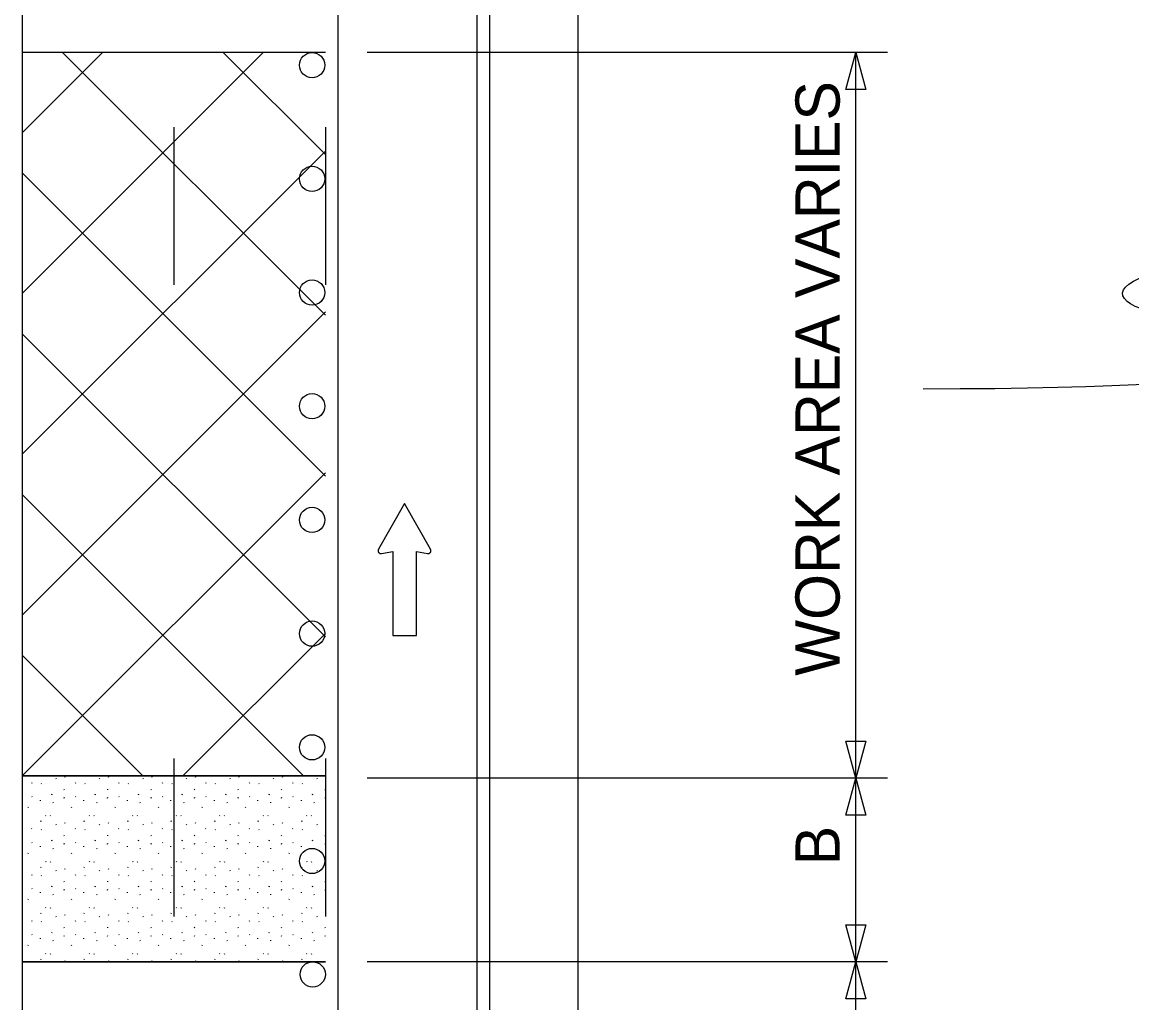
# Model space of a CAD drawing. Extents: x 16782 to 19504, y 6935 to 8243.
# Drawn here: x 17983.1 to 18158.8, y 7895 to 8050.2 of the extents above; entities that cross this region are included whole.
import ezdxf

# ---------------------------------------------------------------- set-up
doc = ezdxf.new("R2010")
doc.units = 0
for name, color, linetype in [('ALI_LEGAL_EX', 7, 'Continuous'), ('MT_SCRATCH_LEVEL_A', 7, 'Continuous'), ('MT_SCRATCH_LEVEL_E', 7, 'Continuous'), ('PAVT_EDGE_EX', 7, 'Continuous'), ('TRAFFIC_SIGNS_PR', 7, 'Continuous'), ('TYPICAL_TEXT_DIMEN_PR', 7, 'Continuous')]:
    doc.layers.add(name, color=color, linetype=linetype)

msp = doc.modelspace()

# ---------------------------------------------------------------- linework, layer by layer
at = {"layer": 'ALI_LEGAL_EX'}
for p, q in [((18033.11, 8234.45), (18033.11, 7405.27)), ((18057.11, 8234.45), (18057.11, 7405.27)), ((18057.11, 8234.45), (18057.11, 7405.27))]:
    msp.add_line(p, q, dxfattribs=at)
for points in [[(18007.13, 8033.65), (18007.13, 8008.65)], [(18031.13, 8033.65), (18031.13, 8008.65)], [(18007.13, 7933.65), (18007.13, 7908.65)], [(18031.13, 7933.65), (18031.13, 7908.65)]]:
    msp.add_lwpolyline(points, dxfattribs=at)
at = {"layer": 'MT_SCRATCH_LEVEL_A'}
for p, q in [((18031.13, 8045.46), (17983.13, 8045.46)), ((18031.13, 7930.92), (17983.13, 7930.92)), ((18031.13, 7901.49), (17983.13, 7901.49))]:
    msp.add_line(p, q, dxfattribs=at)
at = {"layer": 'MT_SCRATCH_LEVEL_E'}
for p, q in [((18043.65, 7974.03), (18039.54, 7966.79)), ((18047.8, 7966.79), (18043.65, 7974.03)), ((18040.03, 7966.11), (18041.8, 7966.42)), ((18041.8, 7966.42), (18041.8, 7953.17)), ((18045.54, 7953.17), (18045.54, 7966.42)), ((18045.54, 7966.42), (18047.32, 7966.11)), ((18041.8, 7953.17), (18045.54, 7953.17))]:
    msp.add_line(p, q, dxfattribs=at)
for centre, start, end in [((18039.95, 7966.57), 150.4248, 279.9638), ((18047.39, 7966.57), 260.0362, 29.7731)]:
    msp.add_arc(centre, 0.463, start, end, dxfattribs=at)
at = {"layer": 'PAVT_EDGE_EX'}
for p, q in [((17983.13, 8183.26), (17983.13, 7404.46)), ((18055.13, 8183.26), (18055.13, 7404.46)), ((18071.13, 8183.26), (18071.13, 7404.46)), ((18031.13, 8045.46), (17983.13, 8045.46)), ((17983.13, 8045.46), (17983.13, 7930.92)), ((17983.13, 8032.74), (17995.84, 8045.46)), ((17983.13, 8007.29), (18021.3, 8045.46)), ((18031.13, 8003.84), (17989.51, 8045.46)), ((18031.13, 8029.29), (18014.96, 8045.46)), ((17983.13, 7981.83), (18031.13, 8029.83)), ((18031.13, 7978.38), (17983.13, 8026.38)), ((17983.13, 7956.38), (18031.13, 8004.38)), ((18031.13, 7952.93), (17983.13, 8000.93)), ((17983.13, 7930.92), (18031.13, 7978.92)), ((18027.67, 7930.92), (17983.13, 7975.47)), ((18008.58, 7930.92), (18031.13, 7953.47)), ((18002.22, 7930.92), (17983.13, 7950.01)), ((17983.13, 7930.92), (18031.13, 7930.92)), ((18031.13, 7930.92), (17983.13, 7930.92)), ((17983.13, 7930.92), (17983.13, 7901.49)), ((17983.13, 7930.92), (17983.13, 7930.92)), ((17984.62, 7929.87), (17984.68, 7929.79)), ((17986.15, 7929.73), (17986.21, 7929.65)), ((17988.44, 7930.55), (17988.5, 7930.47)), ((17989.89, 7930.7), (17989.94, 7930.82)), ((17991.51, 7929.87), (17991.56, 7929.79)), ((17993.04, 7929.73), (17993.09, 7929.65)), ((17995.33, 7930.55), (17995.38, 7930.47)), ((17996.78, 7930.7), (17996.83, 7930.82)), ((17998.4, 7929.87), (17998.45, 7929.79)), ((17999.93, 7929.73), (17999.98, 7929.65)), ((18002.22, 7930.55), (18002.27, 7930.47)), ((18003.67, 7930.7), (18003.72, 7930.82)), ((18005.29, 7929.87), (18005.34, 7929.79)), ((18006.82, 7929.73), (18006.87, 7929.65)), ((18009.11, 7930.55), (18009.16, 7930.47)), ((18010.56, 7930.7), (18010.61, 7930.82)), ((18012.17, 7929.87), (18012.23, 7929.79)), ((18013.7, 7929.73), (18013.76, 7929.65)), ((18015.99, 7930.55), (18016.05, 7930.47)), ((18017.44, 7930.7), (18017.49, 7930.82)), ((18019.06, 7929.87), (18019.11, 7929.79)), ((18020.59, 7929.73), (18020.64, 7929.65)), ((18022.88, 7930.55), (18022.93, 7930.47)), ((18024.33, 7930.7), (18024.38, 7930.82)), ((18025.95, 7929.87), (18026, 7929.79)), ((18027.48, 7929.73), (18027.53, 7929.65)), ((18029.77, 7930.55), (18029.82, 7930.47)), ((17987.8, 7927.94), (17987.85, 7928.06)), ((17989.72, 7928.81), (17989.77, 7928.73)), ((17994.68, 7927.94), (17994.74, 7928.06)), ((17996.61, 7928.81), (17996.66, 7928.73)), ((18001.57, 7927.94), (18001.62, 7928.06)), ((18003.5, 7928.81), (18003.55, 7928.73)), ((18008.46, 7927.94), (18008.51, 7928.06)), ((18010.38, 7928.81), (18010.44, 7928.73)), ((18015.35, 7927.94), (18015.4, 7928.06)), ((18017.27, 7928.81), (18017.32, 7928.73)), ((18022.23, 7927.94), (18022.28, 7928.06)), ((18024.16, 7928.81), (18024.21, 7928.73)), ((18029.12, 7927.94), (18029.17, 7928.06)), ((18031.05, 7928.81), (18031.1, 7928.73)), ((17984.67, 7927.66), (17984.72, 7927.58)), ((17985.95, 7927.09), (17985.97, 7926.97)), ((17987.98, 7926.74), (17988.04, 7926.66)), ((17989.76, 7927.41), (17989.81, 7927.53)), ((17991.56, 7927.66), (17991.61, 7927.58)), ((17992.84, 7927.09), (17992.85, 7926.97)), ((17994.87, 7926.74), (17994.92, 7926.66)), ((17996.65, 7927.41), (17996.7, 7927.53)), ((17998.45, 7927.66), (17998.5, 7927.58)), ((17999.73, 7927.09), (17999.74, 7926.97)), ((18001.76, 7926.74), (18001.81, 7926.66)), ((18003.54, 7927.41), (18003.59, 7927.53)), ((18005.33, 7927.66), (18005.39, 7927.58)), ((18006.62, 7927.09), (18006.63, 7926.97)), ((18008.65, 7926.74), (18008.7, 7926.66)), ((18010.43, 7927.41), (18010.48, 7927.53)), ((18012.22, 7927.66), (18012.27, 7927.58)), ((18013.5, 7927.09), (18013.52, 7926.97)), ((18015.53, 7926.74), (18015.59, 7926.66)), ((18017.31, 7927.41), (18017.37, 7927.53)), ((18019.11, 7927.66), (18019.16, 7927.58)), ((18020.39, 7927.09), (18020.4, 7926.97)), ((18022.42, 7926.74), (18022.47, 7926.66)), ((18024.2, 7927.41), (18024.25, 7927.53)), ((18026, 7927.66), (18026.05, 7927.58)), ((18027.28, 7927.09), (18027.29, 7926.97)), ((18029.31, 7926.74), (18029.36, 7926.66)), ((18031.09, 7927.41), (18031.13, 7927.5)), ((17984.05, 7925.91), (17984.11, 7926.03)), ((17986.84, 7924.67), (17986.89, 7924.6)), ((17987.58, 7924.64), (17987.63, 7924.57)), ((17990.94, 7925.91), (17990.99, 7926.03)), ((17993.73, 7924.67), (17993.78, 7924.6)), ((17994.46, 7924.64), (17994.51, 7924.57)), ((17997.83, 7925.91), (17997.88, 7926.03)), ((18000.61, 7924.67), (18000.67, 7924.6)), ((18001.35, 7924.64), (18001.4, 7924.57)), ((18004.72, 7925.91), (18004.77, 7926.03)), ((18007.5, 7924.67), (18007.55, 7924.6)), ((18008.24, 7924.64), (18008.29, 7924.57)), ((18011.6, 7925.91), (18011.66, 7926.03)), ((18014.39, 7924.67), (18014.44, 7924.6)), ((18015.12, 7924.64), (18015.18, 7924.57)), ((18018.49, 7925.91), (18018.54, 7926.03)), ((18021.28, 7924.67), (18021.33, 7924.6)), ((18022.01, 7924.64), (18022.06, 7924.57)), ((18025.38, 7925.91), (18025.43, 7926.03)), ((18028.16, 7924.67), (18028.22, 7924.6)), ((18028.9, 7924.64), (18028.95, 7924.57)), ((17984.62, 7922.59), (17984.68, 7922.51)), ((17986.07, 7923.71), (17986.13, 7923.83)), ((17988.44, 7923.26), (17988.5, 7923.19)), ((17989.89, 7923.41), (17989.94, 7923.53)), ((17991.51, 7922.59), (17991.56, 7922.51)), ((17992.96, 7923.71), (17993.01, 7923.83)), ((17995.33, 7923.26), (17995.38, 7923.19)), ((17996.78, 7923.41), (17996.83, 7923.53)), ((17998.4, 7922.59), (17998.45, 7922.51)), ((17999.85, 7923.71), (17999.9, 7923.83)), ((18002.22, 7923.26), (18002.27, 7923.19)), ((18003.67, 7923.41), (18003.72, 7923.53)), ((18005.29, 7922.59), (18005.34, 7922.51)), ((18006.74, 7923.71), (18006.79, 7923.83)), ((18009.11, 7923.26), (18009.16, 7923.19)), ((18010.56, 7923.41), (18010.61, 7923.53)), ((18012.17, 7922.59), (18012.23, 7922.51)), ((18013.62, 7923.71), (18013.68, 7923.83)), ((18015.99, 7923.26), (18016.05, 7923.19)), ((18017.44, 7923.41), (18017.49, 7923.53)), ((18019.06, 7922.59), (18019.11, 7922.51)), ((18020.51, 7923.71), (18020.56, 7923.83)), ((18022.88, 7923.26), (18022.93, 7923.19)), ((18024.33, 7923.41), (18024.38, 7923.53)), ((18025.95, 7922.59), (18026, 7922.51)), ((18027.4, 7923.71), (18027.45, 7923.83)), ((18029.77, 7923.26), (18029.82, 7923.19)), ((17986.15, 7922.45), (17986.21, 7922.37)), ((17989.72, 7921.53), (17989.77, 7921.45)), ((17993.04, 7922.45), (17993.09, 7922.37)), ((17996.61, 7921.53), (17996.66, 7921.45)), ((17999.93, 7922.45), (17999.98, 7922.37)), ((18003.5, 7921.53), (18003.55, 7921.45)), ((18006.82, 7922.45), (18006.87, 7922.37)), ((18010.38, 7921.53), (18010.44, 7921.45)), ((18013.7, 7922.45), (18013.76, 7922.37)), ((18017.27, 7921.53), (18017.32, 7921.45)), ((18020.59, 7922.45), (18020.64, 7922.37)), ((18024.16, 7921.53), (18024.21, 7921.45)), ((18027.48, 7922.45), (18027.53, 7922.37)), ((18031.05, 7921.53), (18031.1, 7921.45)), ((17984.67, 7920.38), (17984.72, 7920.3)), ((17985.95, 7919.8), (17985.97, 7919.68)), ((17987.8, 7920.66), (17987.85, 7920.77)), ((17987.98, 7919.46), (17988.04, 7919.38)), ((17989.76, 7920.13), (17989.81, 7920.24)), ((17991.56, 7920.38), (17991.61, 7920.3)), ((17992.84, 7919.8), (17992.85, 7919.68)), ((17994.68, 7920.66), (17994.74, 7920.77)), ((17994.87, 7919.46), (17994.92, 7919.38)), ((17996.65, 7920.13), (17996.7, 7920.24)), ((17998.45, 7920.38), (17998.5, 7920.3)), ((17999.73, 7919.8), (17999.74, 7919.68)), ((18001.57, 7920.66), (18001.62, 7920.77)), ((18001.76, 7919.46), (18001.81, 7919.38)), ((18003.54, 7920.13), (18003.59, 7920.24)), ((18005.33, 7920.38), (18005.39, 7920.3)), ((18006.62, 7919.8), (18006.63, 7919.68)), ((18008.46, 7920.66), (18008.51, 7920.77)), ((18008.65, 7919.46), (18008.7, 7919.38)), ((18010.43, 7920.13), (18010.48, 7920.24)), ((18012.22, 7920.38), (18012.27, 7920.3)), ((18013.5, 7919.8), (18013.52, 7919.68)), ((18015.35, 7920.66), (18015.4, 7920.77)), ((18015.53, 7919.46), (18015.59, 7919.38)), ((18017.31, 7920.13), (18017.37, 7920.24)), ((18019.11, 7920.38), (18019.16, 7920.3)), ((18020.39, 7919.8), (18020.4, 7919.68)), ((18022.23, 7920.66), (18022.28, 7920.77)), ((18022.42, 7919.46), (18022.47, 7919.38)), ((18024.2, 7920.13), (18024.25, 7920.24)), ((18026, 7920.38), (18026.05, 7920.3)), ((18027.28, 7919.8), (18027.29, 7919.68)), ((18029.12, 7920.66), (18029.17, 7920.77)), ((18029.31, 7919.46), (18029.36, 7919.38)), ((18031.09, 7920.13), (18031.13, 7920.21)), ((17984.05, 7918.62), (17984.11, 7918.74)), ((17986.84, 7917.39), (17986.89, 7917.31)), ((17987.58, 7917.36), (17987.63, 7917.28)), ((17990.94, 7918.62), (17990.99, 7918.74)), ((17993.73, 7917.39), (17993.78, 7917.31)), ((17994.46, 7917.36), (17994.51, 7917.28)), ((17997.83, 7918.62), (17997.88, 7918.74)), ((18000.61, 7917.39), (18000.67, 7917.31)), ((18001.35, 7917.36), (18001.4, 7917.28)), ((18004.72, 7918.62), (18004.77, 7918.74)), ((18007.5, 7917.39), (18007.55, 7917.31)), ((18008.24, 7917.36), (18008.29, 7917.28)), ((18011.6, 7918.62), (18011.66, 7918.74)), ((18014.39, 7917.39), (18014.44, 7917.31)), ((18015.12, 7917.36), (18015.18, 7917.28)), ((18018.49, 7918.62), (18018.54, 7918.74)), ((18021.28, 7917.39), (18021.33, 7917.31)), ((18022.01, 7917.36), (18022.06, 7917.28)), ((18025.38, 7918.62), (18025.43, 7918.74)), ((18028.16, 7917.39), (18028.22, 7917.31)), ((18028.9, 7917.36), (18028.95, 7917.28)), ((17986.07, 7916.43), (17986.13, 7916.54)), ((17988.44, 7915.98), (17988.5, 7915.9)), ((17989.89, 7916.13), (17989.94, 7916.25)), ((17992.96, 7916.43), (17993.01, 7916.54)), ((17995.33, 7915.98), (17995.38, 7915.9)), ((17996.78, 7916.13), (17996.83, 7916.25)), ((17999.85, 7916.43), (17999.9, 7916.54)), ((18002.22, 7915.98), (18002.27, 7915.9)), ((18003.67, 7916.13), (18003.72, 7916.25)), ((18006.74, 7916.43), (18006.79, 7916.54)), ((18009.11, 7915.98), (18009.16, 7915.9)), ((18010.56, 7916.13), (18010.61, 7916.25)), ((18013.62, 7916.43), (18013.68, 7916.54)), ((18015.99, 7915.98), (18016.05, 7915.9)), ((18017.44, 7916.13), (18017.49, 7916.25)), ((18020.51, 7916.43), (18020.56, 7916.54)), ((18022.88, 7915.98), (18022.93, 7915.9)), ((18024.33, 7916.13), (18024.38, 7916.25)), ((18027.4, 7916.43), (18027.45, 7916.54)), ((18029.77, 7915.98), (18029.82, 7915.9)), ((17984.62, 7915.3), (17984.68, 7915.22)), ((17986.15, 7915.16), (17986.21, 7915.08)), ((17989.72, 7914.24), (17989.77, 7914.16)), ((17991.51, 7915.3), (17991.56, 7915.22)), ((17993.04, 7915.16), (17993.09, 7915.08)), ((17996.61, 7914.24), (17996.66, 7914.16)), ((17998.4, 7915.3), (17998.45, 7915.22)), ((17999.93, 7915.16), (17999.98, 7915.08)), ((18003.5, 7914.24), (18003.55, 7914.16)), ((18005.29, 7915.3), (18005.34, 7915.22)), ((18006.82, 7915.16), (18006.87, 7915.08)), ((18010.38, 7914.24), (18010.44, 7914.16)), ((18012.17, 7915.3), (18012.23, 7915.22)), ((18013.7, 7915.16), (18013.76, 7915.08)), ((18017.27, 7914.24), (18017.32, 7914.16)), ((18019.06, 7915.3), (18019.11, 7915.22)), ((18020.59, 7915.16), (18020.64, 7915.08)), ((18024.16, 7914.24), (18024.21, 7914.16)), ((18025.95, 7915.3), (18026, 7915.22)), ((18027.48, 7915.16), (18027.53, 7915.08)), ((18031.05, 7914.24), (18031.1, 7914.16)), ((17984.67, 7913.09), (17984.72, 7913.01)), ((17985.95, 7912.52), (17985.97, 7912.4)), ((17987.8, 7913.37), (17987.85, 7913.49)), ((17987.98, 7912.17), (17988.04, 7912.1)), ((17989.76, 7912.84), (17989.81, 7912.96)), ((17991.56, 7913.09), (17991.61, 7913.01)), ((17992.84, 7912.52), (17992.85, 7912.4)), ((17994.68, 7913.37), (17994.74, 7913.49)), ((17994.87, 7912.17), (17994.92, 7912.1)), ((17996.65, 7912.84), (17996.7, 7912.96)), ((17998.45, 7913.09), (17998.5, 7913.01)), ((17999.73, 7912.52), (17999.74, 7912.4)), ((18001.57, 7913.37), (18001.62, 7913.49)), ((18001.76, 7912.17), (18001.81, 7912.1)), ((18003.54, 7912.84), (18003.59, 7912.96)), ((18005.33, 7913.09), (18005.39, 7913.01)), ((18006.62, 7912.52), (18006.63, 7912.4)), ((18008.46, 7913.37), (18008.51, 7913.49)), ((18008.65, 7912.17), (18008.7, 7912.1)), ((18010.43, 7912.84), (18010.48, 7912.96)), ((18012.22, 7913.09), (18012.27, 7913.01)), ((18013.5, 7912.52), (18013.52, 7912.4)), ((18015.35, 7913.37), (18015.4, 7913.49)), ((18015.53, 7912.17), (18015.59, 7912.1)), ((18017.31, 7912.84), (18017.37, 7912.96)), ((18019.11, 7913.09), (18019.16, 7913.01)), ((18020.39, 7912.52), (18020.4, 7912.4)), ((18022.23, 7913.37), (18022.28, 7913.49)), ((18022.42, 7912.17), (18022.47, 7912.1)), ((18024.2, 7912.84), (18024.25, 7912.96)), ((18026, 7913.09), (18026.05, 7913.01)), ((18027.28, 7912.52), (18027.29, 7912.4)), ((18029.12, 7913.37), (18029.17, 7913.49)), ((18029.31, 7912.17), (18029.36, 7912.1)), ((18031.09, 7912.84), (18031.13, 7912.93)), ((17984.05, 7911.34), (17984.11, 7911.46)), ((17990.94, 7911.34), (17990.99, 7911.46)), ((17997.83, 7911.34), (17997.88, 7911.46)), ((18004.72, 7911.34), (18004.77, 7911.46)), ((18011.6, 7911.34), (18011.66, 7911.46)), ((18018.49, 7911.34), (18018.54, 7911.46)), ((18025.38, 7911.34), (18025.43, 7911.46)), ((17986.07, 7909.14), (17986.13, 7909.26)), ((17986.84, 7910.1), (17986.89, 7910.03)), ((17987.58, 7910.07), (17987.63, 7909.99)), ((17988.44, 7908.69), (17988.5, 7908.62)), ((17989.89, 7908.85), (17989.94, 7908.96)), ((17992.96, 7909.14), (17993.01, 7909.26)), ((17993.73, 7910.1), (17993.78, 7910.03)), ((17994.46, 7910.07), (17994.51, 7909.99)), ((17995.33, 7908.69), (17995.38, 7908.62)), ((17996.78, 7908.85), (17996.83, 7908.96)), ((17999.85, 7909.14), (17999.9, 7909.26)), ((18000.61, 7910.1), (18000.67, 7910.03)), ((18001.35, 7910.07), (18001.4, 7909.99)), ((18002.22, 7908.69), (18002.27, 7908.62)), ((18003.67, 7908.85), (18003.72, 7908.96)), ((18006.74, 7909.14), (18006.79, 7909.26)), ((18007.5, 7910.1), (18007.55, 7910.03)), ((18008.24, 7910.07), (18008.29, 7909.99)), ((18009.11, 7908.69), (18009.16, 7908.62)), ((18010.56, 7908.85), (18010.61, 7908.96)), ((18013.62, 7909.14), (18013.68, 7909.26)), ((18014.39, 7910.1), (18014.44, 7910.03)), ((18015.12, 7910.07), (18015.18, 7909.99)), ((18015.99, 7908.69), (18016.05, 7908.62)), ((18017.44, 7908.85), (18017.49, 7908.96)), ((18020.51, 7909.14), (18020.56, 7909.26)), ((18021.28, 7910.1), (18021.33, 7910.03)), ((18022.01, 7910.07), (18022.06, 7909.99)), ((18022.88, 7908.69), (18022.93, 7908.62)), ((18024.33, 7908.85), (18024.38, 7908.96)), ((18027.4, 7909.14), (18027.45, 7909.26)), ((18028.16, 7910.1), (18028.22, 7910.03)), ((18028.9, 7910.07), (18028.95, 7909.99)), ((18029.77, 7908.69), (18029.82, 7908.62)), ((17984.62, 7908.02), (17984.68, 7907.94)), ((17986.15, 7907.88), (17986.21, 7907.8)), ((17989.72, 7906.96), (17989.77, 7906.88)), ((17991.51, 7908.02), (17991.56, 7907.94)), ((17993.04, 7907.88), (17993.09, 7907.8)), ((17996.61, 7906.96), (17996.66, 7906.88)), ((17998.4, 7908.02), (17998.45, 7907.94)), ((17999.93, 7907.88), (17999.98, 7907.8)), ((18003.5, 7906.96), (18003.55, 7906.88)), ((18005.29, 7908.02), (18005.34, 7907.94)), ((18006.82, 7907.88), (18006.87, 7907.8)), ((18010.38, 7906.96), (18010.44, 7906.88)), ((18012.17, 7908.02), (18012.23, 7907.94)), ((18013.7, 7907.88), (18013.76, 7907.8)), ((18017.27, 7906.96), (18017.32, 7906.88)), ((18019.06, 7908.02), (18019.11, 7907.94)), ((18020.59, 7907.88), (18020.64, 7907.8)), ((18024.16, 7906.96), (18024.21, 7906.88)), ((18025.95, 7908.02), (18026, 7907.94)), ((18027.48, 7907.88), (18027.53, 7907.8)), ((18031.05, 7906.96), (18031.1, 7906.88)), ((17984.67, 7905.81), (17984.72, 7905.73)), ((17985.95, 7905.23), (17985.97, 7905.11)), ((17987.8, 7906.09), (17987.85, 7906.2)), ((17989.76, 7905.56), (17989.81, 7905.67)), ((17991.56, 7905.81), (17991.61, 7905.73)), ((17992.84, 7905.23), (17992.85, 7905.11)), ((17994.68, 7906.09), (17994.74, 7906.2)), ((17996.65, 7905.56), (17996.7, 7905.67)), ((17998.45, 7905.81), (17998.5, 7905.73)), ((17999.73, 7905.23), (17999.74, 7905.11)), ((18001.57, 7906.09), (18001.62, 7906.2)), ((18003.54, 7905.56), (18003.59, 7905.67)), ((18005.33, 7905.81), (18005.39, 7905.73)), ((18006.62, 7905.23), (18006.63, 7905.11)), ((18008.46, 7906.09), (18008.51, 7906.2)), ((18010.43, 7905.56), (18010.48, 7905.67)), ((18012.22, 7905.81), (18012.27, 7905.73)), ((18013.5, 7905.23), (18013.52, 7905.11)), ((18015.35, 7906.09), (18015.4, 7906.2)), ((18017.31, 7905.56), (18017.37, 7905.67)), ((18019.11, 7905.81), (18019.16, 7905.73)), ((18020.39, 7905.23), (18020.4, 7905.11)), ((18022.23, 7906.09), (18022.28, 7906.2)), ((18024.2, 7905.56), (18024.25, 7905.67)), ((18026, 7905.81), (18026.05, 7905.73)), ((18027.28, 7905.23), (18027.29, 7905.11)), ((18029.12, 7906.09), (18029.17, 7906.2)), ((18031.09, 7905.56), (18031.13, 7905.64)), ((17984.05, 7904.05), (17984.11, 7904.17)), ((17987.98, 7904.89), (17988.04, 7904.81)), ((17990.94, 7904.05), (17990.99, 7904.17)), ((17994.87, 7904.89), (17994.92, 7904.81)), ((17997.83, 7904.05), (17997.88, 7904.17)), ((18001.76, 7904.89), (18001.81, 7904.81)), ((18004.72, 7904.05), (18004.77, 7904.17)), ((18008.65, 7904.89), (18008.7, 7904.81)), ((18011.6, 7904.05), (18011.66, 7904.17)), ((18015.53, 7904.89), (18015.59, 7904.81)), ((18018.49, 7904.05), (18018.54, 7904.17)), ((18022.42, 7904.89), (18022.47, 7904.81)), ((18025.38, 7904.05), (18025.43, 7904.17)), ((18029.31, 7904.89), (18029.36, 7904.81)), ((17983.13, 7901.49), (18031.13, 7901.49)), ((17986.07, 7901.86), (17986.13, 7901.97)), ((17986.84, 7902.82), (17986.89, 7902.74)), ((17987.58, 7902.79), (17987.63, 7902.71)), ((17989.89, 7901.56), (17989.94, 7901.68)), ((17992.96, 7901.86), (17993.01, 7901.97)), ((17993.73, 7902.82), (17993.78, 7902.74)), ((17994.46, 7902.79), (17994.51, 7902.71)), ((17996.78, 7901.56), (17996.83, 7901.68)), ((17999.85, 7901.86), (17999.9, 7901.97)), ((18000.61, 7902.82), (18000.67, 7902.74)), ((18001.35, 7902.79), (18001.4, 7902.71)), ((18003.67, 7901.56), (18003.72, 7901.68)), ((18006.74, 7901.86), (18006.79, 7901.97)), ((18007.5, 7902.82), (18007.55, 7902.74)), ((18008.24, 7902.79), (18008.29, 7902.71)), ((18010.56, 7901.56), (18010.61, 7901.68)), ((18013.62, 7901.86), (18013.68, 7901.97)), ((18014.39, 7902.82), (18014.44, 7902.74)), ((18015.12, 7902.79), (18015.18, 7902.71)), ((18017.44, 7901.56), (18017.49, 7901.68)), ((18020.51, 7901.86), (18020.56, 7901.97)), ((18021.28, 7902.82), (18021.33, 7902.74)), ((18022.01, 7902.79), (18022.06, 7902.71)), ((18024.33, 7901.56), (18024.38, 7901.68)), ((18027.4, 7901.86), (18027.45, 7901.97)), ((18028.16, 7902.82), (18028.22, 7902.74)), ((18028.9, 7902.79), (18028.95, 7902.71))]:
    msp.add_line(p, q, dxfattribs=at)
at = {"layer": 'TRAFFIC_SIGNS_PR'}
for centre in [(18029.03, 8043.44), (18029.03, 8025.44), (18029.03, 8007.44), (18029.03, 7989.44), (18029.03, 7971.44), (18029.03, 7953.44), (18029.03, 7935.44), (18029.03, 7917.44), (18029.13, 7899.49)]:
    msp.add_circle(centre, 2, dxfattribs=at)
at = {"layer": 'TYPICAL_TEXT_DIMEN_PR'}
for p, q in [((18120.13, 8045.46), (18037.73, 8045.46)), ((18113.56, 8039.6), (18115.13, 8045.46)), ((18115.13, 7930.55), (18115.13, 8045.46)), ((18115.13, 8045.46), (18116.7, 8039.6)), ((18115.13, 8039.6), (18113.56, 8039.6)), ((18116.7, 8039.6), (18115.13, 8039.6)), ((18115.13, 7930.55), (18113.56, 7936.41)), ((18113.56, 7936.41), (18115.13, 7936.41)), ((18115.13, 7936.41), (18116.7, 7936.41)), ((18116.7, 7936.41), (18115.13, 7930.55)), ((18120.13, 7930.55), (18037.73, 7930.55)), ((18113.56, 7924.69), (18115.13, 7930.55)), ((18115.13, 7901.49), (18115.13, 7930.55)), ((18115.13, 7930.55), (18116.7, 7924.69)), ((18115.13, 7924.69), (18113.56, 7924.69)), ((18116.7, 7924.69), (18115.13, 7924.69)), ((18115.13, 7901.49), (18113.56, 7907.36)), ((18113.56, 7907.36), (18115.13, 7907.36)), ((18115.13, 7907.36), (18116.7, 7907.36)), ((18116.7, 7907.36), (18115.13, 7901.49)), ((18120.13, 7901.49), (18037.73, 7901.49)), ((18113.56, 7895.63), (18115.13, 7901.49)), ((18115.13, 7870.93), (18115.13, 7901.49)), ((18115.13, 7901.49), (18116.7, 7895.63)), ((18115.13, 7895.63), (18113.56, 7895.63)), ((18116.7, 7895.63), (18115.13, 7895.63))]:
    msp.add_line(p, q, dxfattribs=at)
msp.add_open_spline([(18125.79, 7992.21), (18190.37, 7992.21), (18190.37, 8002.97), (18155.45, 8002.97), (18155.45, 8012.63), (18198.31, 8014.15), (18210.22, 8014.41)], degree=3, dxfattribs=at)

# ---------------------------------------------------------------- texts
for s, p in [('WORK AREA VARIES', (18112.57, 7946.77)), ('B', (18112.57, 7916.76))]:
    msp.add_text(s, height=7, rotation=90, dxfattribs=at).set_placement(p)

doc.saveas('drawing.dxf')
